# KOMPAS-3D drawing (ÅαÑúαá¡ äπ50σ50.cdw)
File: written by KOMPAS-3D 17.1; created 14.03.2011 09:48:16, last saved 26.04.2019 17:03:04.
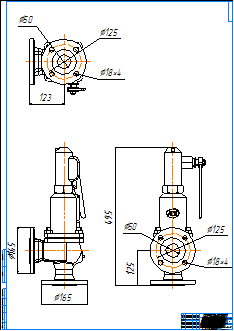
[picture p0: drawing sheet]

Sheet 1: A0, portrait

Title block, sheet 1: name: Прегран Ду50х50; material: Внимание! Данный продукт является объектом авторского права ООО «Торговый Дом АДЛ». / Запрещается изменение, копирование, распространение / (в том числе путем копирования на другие сайты и ресурсы в Интернете) / или любое иное использование информации и объектов без предварительного / согласия правообладателя (ООО «Торговый Дом АДЛ»).; scale: 1:1; sheets: 1; organisation: ООО "Торговый дом АДЛ"; sheet format: A0; stored path: C:\Users\tra\Desktop\2д чертежи\Предохранительные клапаны ПРЕГРАН\ПРЕГРАН 096\ПРЕГРАН КПП 096-03-40\KOMPAS 2D\Прегран Ду50х50.cdw

Views: Проекционный вид 2, Проекционный вид 3, Проекционный вид 4
Dimensions and other numbers on the sheet: 125; 18; 50; 165; 123; 495; 1:1; 1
